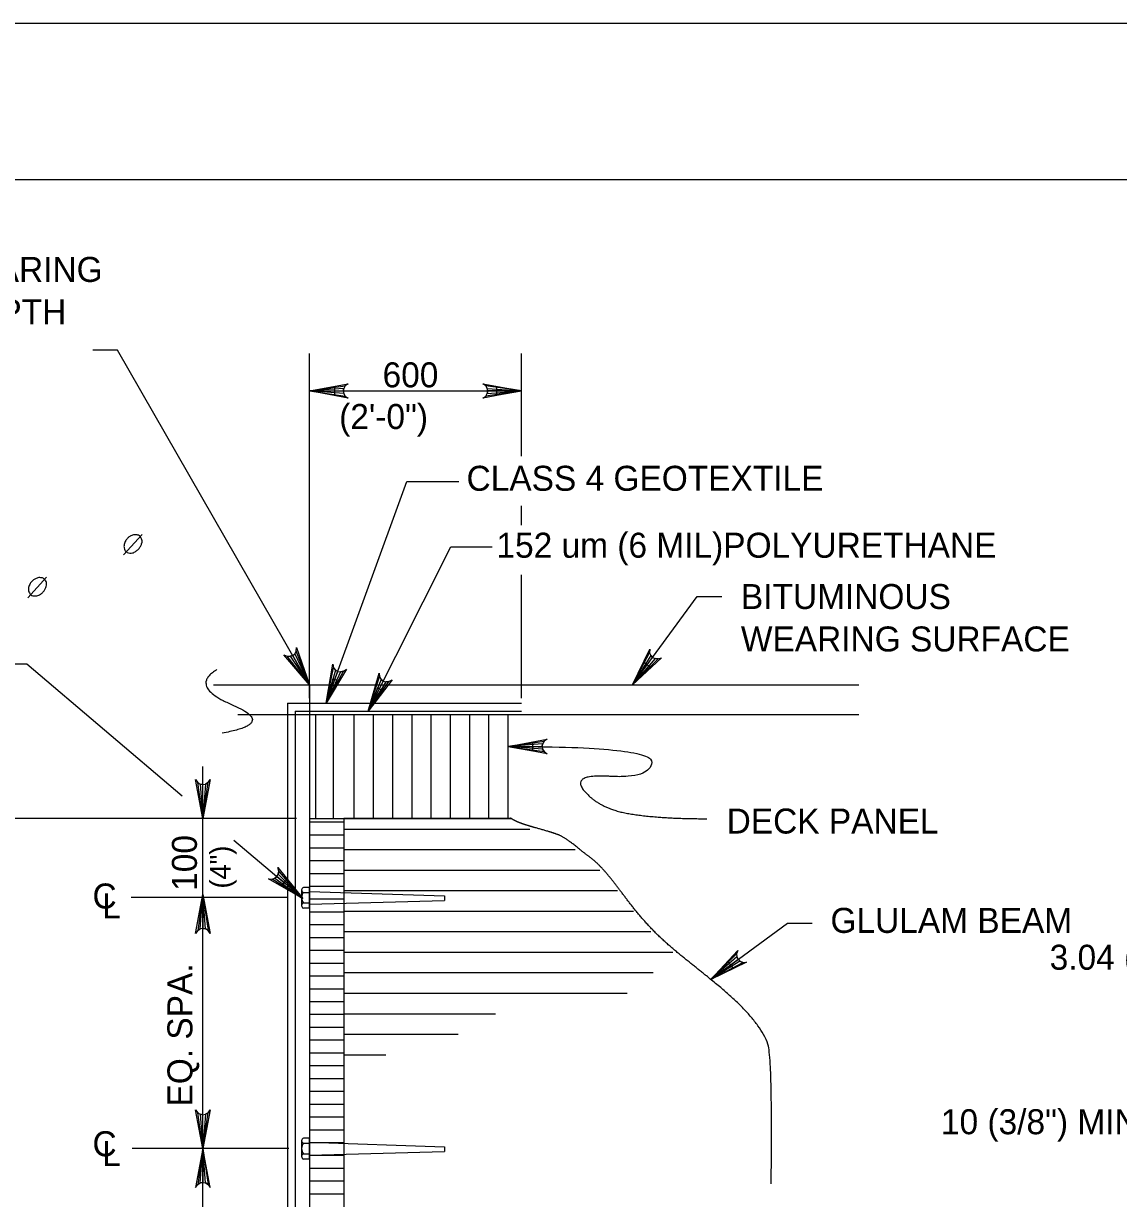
# Model space of a CAD drawing. Extents: x -13 to 81, y -176 to 0.
# Drawn here: x 47.85 to 53.11, y -5.64 to 0 of the extents above; entities that cross this region are included whole.
import ezdxf

# ---------------------------------------------------------------- set-up
doc = ezdxf.new("R2010")
doc.units = 0
for name, color, linetype in [('Level 1', 7, 'Continuous'), ('Level 3', 7, 'Continuous'), ('Level 4', 7, 'Continuous'), ('Level 5', 7, 'Continuous'), ('Level 52', 7, 'Continuous'), ('Level 63', 7, 'Continuous'), ('Level 7', 7, 'Continuous')]:
    doc.layers.add(name, color=color, linetype=linetype)

msp = doc.modelspace()

# ---------------------------------------------------------------- linework, layer by layer
at = {"layer": 'Level 1'}
msp.add_lwpolyline([(35.75, -21.25), (67.25, -21.25), (67.25, -0.75), (35.75, -0.75)], close=True, dxfattribs=at)
at = {"layer": 'Level 3'}
for p, q in [((49.2237, -3.2382), (49.2237, -1.5837)), ((50.2417, -2.0767), (50.2417, -1.5837)), ((49.2237, -1.7637), (50.2417, -1.7637)), ((49.6906, -2.1984), (49.9411, -2.1984)), ((50.2417, -2.4084), (50.2417, -2.3154)), ((49.903, -2.5117), (50.1011, -2.5117)), ((50.2417, -3.2382), (50.2417, -2.646)), ((50.7744, -3.1736), (51.0846, -2.7508)), ((51.0846, -2.7508), (51.2027, -2.7508)), ((47.8689, -3.0749), (47.6388, -3.0749)), ((48.6134, -3.709), (47.8689, -3.0749)), ((48.7129, -4.1953), (48.7129, -3.5662)), ((49.1623, -3.8148), (47.2889, -3.8148)), ((49.1074, -4.1297), (48.8619, -3.9206)), ((49.1163, -4.1953), (48.3682, -4.1953)), ((48.7129, -5.2816), (48.7129, -4.1807)), ((51.1491, -4.5874), (51.5173, -4.3172)), ((51.5173, -4.3172), (51.6354, -4.3172)), ((49.1248, -5.3997), (48.3735, -5.3997)), ((48.7129, -6.6186), (48.7129, -5.3997))]:
    msp.add_line(p, q, dxfattribs=at)
for points in [[(49.2237, -1.7637), (49.4102, -1.7288), (49.3958, -1.7388), (49.3884, -1.7512), (49.3862, -1.7637), (49.3884, -1.7762), (49.3958, -1.7887), (49.4102, -1.7987), (49.2237, -1.7637), (49.3958, -1.7887), (49.3884, -1.7762), (49.2237, -1.7637), (49.3862, -1.7637), (49.3884, -1.7512), (49.2237, -1.7637), (49.3958, -1.7388)], [(50.2417, -1.7637), (50.0553, -1.7987), (50.0696, -1.7887), (50.077, -1.7762), (50.0792, -1.7637), (50.077, -1.7512), (50.0696, -1.7388), (50.0553, -1.7288), (50.2417, -1.7637), (50.0696, -1.7388), (50.077, -1.7512), (50.2417, -1.7637), (50.0792, -1.7637), (50.077, -1.7762), (50.2417, -1.7637), (50.0696, -1.7887)], [(49.3048, -3.2621), (49.6907, -2.1984)], [(49.5052, -3.3007), (49.9031, -2.5117)], [(50.7744, -3.1736), (50.8565, -3.0026), (50.856, -3.0201), (50.8618, -3.0334), (50.8705, -3.0426), (50.8819, -3.0482), (50.8963, -3.0497), (50.9128, -3.0439), (50.7744, -3.1736), (50.8963, -3.0497), (50.8819, -3.0482), (50.7744, -3.1736), (50.8705, -3.0426), (50.8618, -3.0334), (50.7744, -3.1736), (50.856, -3.0201)], [(49.3048, -3.2621), (49.3356, -3.0749), (49.34, -3.0918), (49.3492, -3.1031), (49.3603, -3.1093), (49.3727, -3.1116), (49.387, -3.1088), (49.4012, -3.0987), (49.3048, -3.2621), (49.387, -3.1088), (49.3727, -3.1116), (49.3048, -3.2621), (49.3603, -3.1093), (49.3492, -3.1031), (49.3048, -3.2621), (49.34, -3.0918)], [(49.5052, -3.3007), (49.558, -3.1185), (49.5604, -3.1357), (49.5682, -3.148), (49.5784, -3.1556), (49.5905, -3.1593), (49.605, -3.1583), (49.6204, -3.1499), (49.5052, -3.3007), (49.605, -3.1583), (49.5905, -3.1593), (49.5052, -3.3007), (49.5784, -3.1556), (49.5682, -3.148), (49.5052, -3.3007), (49.5604, -3.1357)], [(50.1774, -3.4695), (50.3638, -3.4346), (50.3495, -3.4445), (50.3421, -3.457), (50.3399, -3.4695), (50.3421, -3.482), (50.3495, -3.4945), (50.3638, -3.5044), (50.1774, -3.4695), (50.3495, -3.4945), (50.3421, -3.482), (50.1774, -3.4695), (50.3399, -3.4695), (50.3421, -3.457), (50.1774, -3.4695), (50.3495, -3.4445)], [(48.7129, -3.8148), (48.678, -3.6283), (48.6879, -3.6427), (48.7004, -3.6501), (48.7129, -3.6522), (48.7254, -3.6501), (48.7379, -3.6427), (48.7478, -3.6283), (48.7129, -3.8148), (48.7379, -3.6427), (48.7254, -3.6501), (48.7129, -3.8148), (48.7129, -3.6522), (48.7004, -3.6501), (48.7129, -3.8148), (48.6879, -3.6427)], [(48.7129, -4.1807), (48.7478, -4.3672), (48.7379, -4.3528), (48.7254, -4.3454), (48.7129, -4.3433), (48.7004, -4.3454), (48.6879, -4.3528), (48.678, -4.3672), (48.7129, -4.1807), (48.6879, -4.3528), (48.7004, -4.3454), (48.7129, -4.1807), (48.7129, -4.3433), (48.7254, -4.3454), (48.7129, -4.1807), (48.7379, -4.3528)], [(51.1491, -4.5874), (51.2787, -4.449), (51.273, -4.4655), (51.2744, -4.4799), (51.2801, -4.4913), (51.2892, -4.5001), (51.3026, -4.5058), (51.3201, -4.5053), (51.1491, -4.5874), (51.3026, -4.5058), (51.2892, -4.5001), (51.1491, -4.5874), (51.2801, -4.4913), (51.2744, -4.4799), (51.1491, -4.5874), (51.273, -4.4655)], [(48.7129, -5.3997), (48.678, -5.2132), (48.6879, -5.2276), (48.7004, -5.235), (48.7129, -5.2372), (48.7254, -5.235), (48.7379, -5.2276), (48.7478, -5.2132), (48.7129, -5.3997), (48.7379, -5.2276), (48.7254, -5.235), (48.7129, -5.3997), (48.7129, -5.2372), (48.7004, -5.235), (48.7129, -5.3997), (48.6879, -5.2276)], [(48.7129, -5.3997), (48.678, -5.5861), (48.6879, -5.5717), (48.7004, -5.5643), (48.7129, -5.5622), (48.7254, -5.5643), (48.7379, -5.5717), (48.7478, -5.5861), (48.7129, -5.3997), (48.7379, -5.5717), (48.7254, -5.5643), (48.7129, -5.3997), (48.7129, -5.5622), (48.7004, -5.5643), (48.7129, -5.3997), (48.6879, -5.5717)]]:
    msp.add_lwpolyline(points, dxfattribs=at)
for points in [[(49.3438, -1.7437), (49.3438, -1.7837), (49.2237, -1.7637)], [(50.1217, -1.7437), (50.1217, -1.7837), (50.2417, -1.7637)], [(50.8601, -3.09), (50.8283, -3.0667), (50.7743, -3.1736)], [(49.3048, -3.2621), (49.3552, -3.1527), (49.3363, -3.1459)], [(49.5052, -3.3007), (49.5682, -3.198), (49.5503, -3.189)], [(50.2952, -3.491), (50.2958, -3.4516), (50.1774, -3.4695)], [(49.1148, -4.1072), (49.0892, -4.1372), (49.1919, -4.1987)], [(51.2562, -4.5333), (51.2329, -4.5016), (51.1493, -4.5873)]]:
    msp.add_lwpolyline(points, close=True, dxfattribs=at)
msp.add_open_spline([(50.1774, -3.4695), (50.8787, -3.4695), (50.8548, -3.6251), (50.4722, -3.6011), (50.6157, -3.7687), (50.9027, -3.8165), (51.1298, -3.8165)], degree=2, dxfattribs=at)
at = {"layer": 'Level 4'}
for p, q in [((48.3314, -2.5499), (48.421, -2.4518)), ((47.8732, -2.7559), (47.9627, -2.6578))]:
    msp.add_line(p, q, dxfattribs=at)
for points in [[(48.4117, -2.4615), (48.4047, -2.4561), (48.3977, -2.4542), (48.389, -2.4534), (48.3838, -2.4534), (48.3753, -2.4553), (48.3673, -2.459), (48.3619, -2.4621), (48.3513, -2.4706), (48.343, -2.4813), (48.338, -2.4914), (48.3351, -2.5007), (48.3342, -2.5093), (48.3351, -2.5167), (48.3387, -2.5272), (48.3426, -2.5327), (48.3502, -2.5386), (48.3618, -2.5413), (48.375, -2.5409), (48.3918, -2.5332), (48.4039, -2.5228), (48.4131, -2.5101), (48.4191, -2.4968), (48.4211, -2.4822), (48.4185, -2.4727), (48.4122, -2.4615)], [(47.9535, -2.6675), (47.9464, -2.6621), (47.9394, -2.6602), (47.9307, -2.6594), (47.9256, -2.6594), (47.9171, -2.6613), (47.9091, -2.665), (47.9037, -2.6681), (47.8931, -2.6766), (47.8847, -2.6873), (47.8798, -2.6974), (47.8768, -2.7067), (47.8759, -2.7153), (47.8768, -2.7227), (47.8805, -2.7332), (47.8843, -2.7387), (47.8919, -2.7446), (47.9035, -2.7473), (47.9168, -2.7469), (47.9335, -2.7392), (47.9457, -2.7288), (47.9548, -2.7161), (47.9608, -2.7028), (47.9628, -2.6882), (47.9602, -2.6787), (47.9539, -2.6675)]]:
    msp.add_spline(points, degree=3, dxfattribs=at)
at = {"layer": 'Level 5'}
for p, q in [((48.3036, -1.567), (48.1855, -1.567)), ((49.2248, -3.1736), (48.3036, -1.567)), ((48.763, -3.1736), (51.8598, -3.1736)), ((49.2237, -3.1736), (49.2237, -7.0929)), ((49.119, -3.2621), (50.2417, -3.2621)), ((49.119, -3.2621), (49.119, -7.198)), ((49.2545, -3.3184), (48.88, -3.3184)), ((49.156, -3.3007), (50.2417, -3.3007)), ((49.156, -3.3007), (49.156, -7.1582)), ((51.8598, -3.3184), (49.2237, -3.3184)), ((49.2237, -3.8148), (50.1907, -3.8148)), ((49.3892, -3.8148), (49.3892, -7.0929)), ((49.1863, -4.1578), (49.1863, -4.2337)), ((49.2237, -4.1655), (49.8712, -4.1874)), ((49.2237, -4.227), (49.8712, -4.2095)), ((49.8712, -4.1874), (49.8712, -4.2095)), ((49.1863, -5.3617), (49.1863, -5.4376)), ((49.2237, -5.3694), (49.8712, -5.3912)), ((49.2237, -5.4308), (49.8712, -5.4134)), ((49.8712, -5.3912), (49.8712, -5.4134))]:
    msp.add_line(p, q, dxfattribs=at)
for points in [[(49.2248, -3.1736), (49.1017, -3.0292), (49.1175, -3.0368), (49.132, -3.037), (49.1439, -3.0326), (49.1537, -3.0245), (49.1608, -3.0119), (49.1623, -2.9945), (49.2248, -3.1736), (49.1608, -3.0119), (49.1537, -3.0245), (49.2248, -3.1736), (49.1439, -3.0326), (49.132, -3.037), (49.2248, -3.1736), (49.1175, -3.0368)], [(50.1907, -3.8148), (50.1743, -3.8148), (49.3892, -3.8148), (49.3892, -6.3787)]]:
    msp.add_lwpolyline(points, dxfattribs=at)
for centre, radius, start, end in [((49.1989, -4.1583), 0.0126, 107.4518, 252.5482), ((49.226, -4.1953), 0.0397, 141.05, 218.95), ((49.2002, -4.2333), 0.0139, 111.2869, 178.1729), ((49.2002, -4.2333), 0.0139, 178.1729, 248.7131), ((49.1989, -5.3622), 0.0126, 107.4518, 252.5482), ((49.226, -5.3992), 0.0397, 141.05, 218.95), ((49.2002, -5.4372), 0.0139, 111.2869, 178.1729), ((49.2002, -5.4372), 0.0139, 178.1729, 248.7131)]:
    msp.add_arc(centre, radius, start, end, dxfattribs=at)
msp.add_open_spline([(48.7797, -3.1011), (48.6452, -3.182), (49.067, -3.3602), (48.8058, -3.4058)], degree=2, dxfattribs=at)
at = {"layer": 'Level 52'}
msp.add_lwpolyline([(49.1919, -4.1987), (49.0273, -4.1045), (49.0448, -4.1063), (49.0585, -4.1015), (49.0682, -4.0934), (49.0747, -4.0825), (49.0772, -4.0682), (49.0727, -4.0512), (49.1919, -4.1987), (49.0772, -4.0682), (49.0747, -4.0825), (49.1919, -4.1987), (49.0682, -4.0934), (49.0585, -4.1015), (49.1919, -4.1987), (49.0448, -4.1063)], dxfattribs=at)
at = {"layer": 'Level 63'}
msp.add_lwpolyline([(34, -22), (68, -22), (68, 0), (34, 0)], close=True, dxfattribs=at)
at = {"layer": 'Level 7'}
for p, q in [((49.2545, -3.8148), (49.2545, -3.3184)), ((49.3388, -3.8148), (49.3388, -3.3184)), ((49.4393, -3.8148), (49.4393, -3.3184)), ((49.5315, -3.8148), (49.5315, -3.3184)), ((49.6238, -3.8148), (49.6238, -3.3184)), ((49.7161, -3.8148), (49.7161, -3.3184)), ((49.8083, -3.8148), (49.8083, -3.3184)), ((49.9007, -3.8148), (49.9007, -3.3184)), ((49.9929, -3.8148), (49.9929, -3.3184)), ((50.0852, -3.8148), (50.0852, -3.3184)), ((50.1774, -3.8148), (50.1774, -3.3184)), ((49.2237, -3.8148), (49.2237, -3.8148)), ((49.2237, -3.8317), (49.3892, -3.8317)), ((49.3892, -3.8148), (49.3892, -3.8148)), ((49.3892, -3.8663), (50.2809, -3.8663)), ((49.2237, -3.8941), (49.3892, -3.8941)), ((49.2237, -3.9556), (49.3892, -3.9556)), ((49.3894, -3.9647), (50.4993, -3.9647)), ((49.2237, -4.0172), (49.3892, -4.0172)), ((49.2237, -4.0787), (49.3892, -4.0787)), ((49.3896, -4.0632), (50.617, -4.0632)), ((49.2237, -4.1463), (49.1952, -4.1463)), ((49.1952, -4.1703), (49.2237, -4.1703)), ((49.2237, -4.1402), (49.3892, -4.1402)), ((49.2237, -4.2462), (49.2237, -4.1463)), ((49.3897, -4.1616), (50.7012, -4.1616)), ((49.1952, -4.2203), (49.2237, -4.2203)), ((49.2237, -4.2017), (49.3892, -4.2017)), ((49.2237, -4.2462), (49.1952, -4.2462)), ((49.2237, -4.2632), (49.3892, -4.2632)), ((49.39, -4.26), (50.7781, -4.26)), ((49.2237, -4.3247), (49.3892, -4.3247)), ((49.2237, -4.3862), (49.3892, -4.3862)), ((49.3902, -4.3585), (50.8622, -4.3585)), ((49.2237, -4.4478), (49.3892, -4.4478)), ((49.2237, -4.5092), (49.3892, -4.5092)), ((49.3903, -4.4569), (50.9671, -4.4569)), ((49.3906, -4.5553), (50.8735, -4.5553)), ((49.2237, -4.5707), (49.3892, -4.5707)), ((49.2237, -4.6322), (49.3892, -4.6322)), ((49.3907, -4.6537), (50.7475, -4.6537)), ((49.2237, -4.6938), (49.3892, -4.6938)), ((49.2237, -4.7553), (49.3892, -4.7553)), ((49.3909, -4.7522), (50.1163, -4.7522)), ((49.2237, -4.8168), (49.3892, -4.8168)), ((49.2237, -4.8783), (49.3892, -4.8783)), ((49.3911, -4.8506), (49.9368, -4.8506)), ((49.2237, -4.9398), (49.3892, -4.9398)), ((49.3913, -4.949), (49.5912, -4.949)), ((49.2237, -5.0014), (49.3892, -5.0014)), ((49.2237, -5.0629), (49.3892, -5.0629)), ((49.2237, -5.1244), (49.3892, -5.1244)), ((49.2237, -5.1859), (49.3892, -5.1859)), ((49.2237, -5.2474), (49.3892, -5.2474)), ((49.2237, -5.3502), (49.1952, -5.3502)), ((49.2237, -5.309), (49.3892, -5.309)), ((49.2237, -5.4501), (49.2237, -5.3502)), ((49.1952, -5.3742), (49.2237, -5.3742)), ((49.2237, -5.3705), (49.3892, -5.3705)), ((49.1952, -5.4242), (49.2237, -5.4242)), ((49.2237, -5.4501), (49.1952, -5.4501)), ((49.2237, -5.432), (49.3892, -5.432)), ((49.2237, -5.4935), (49.3892, -5.4935)), ((49.2237, -5.555), (49.3892, -5.555)), ((49.2237, -5.6165), (49.3892, -5.6165))]:
    msp.add_line(p, q, dxfattribs=at)
msp.add_open_spline([(51.4387, -5.5684), (51.4426, -5.3831), (51.4368, -4.9253), (51.4035, -4.8501), (51.353, -4.7783), (51.2893, -4.7093), (51.2165, -4.6428), (51.1382, -4.5782), (51.0587, -4.5151), (50.9818, -4.4528), (50.9114, -4.3912), (50.8506, -4.3297), (50.7982, -4.2692), (50.7521, -4.2107), (50.7103, -4.1553), (50.6709, -4.1039), (50.6317, -4.0576), (50.5907, -4.0172), (50.5457, -3.984), (50.4464, -3.9043), (50.393, -3.8845), (50.3392, -3.8686), (50.2875, -3.8544), (50.2407, -3.8398), (50.2015, -3.8229), (50.1886, -3.8132)], degree=2, dxfattribs=at)

# ---------------------------------------------------------------- texts
at = {"layer": 'Level 3'}
for s, p in [('SAW CUT BITUMINOUS WEARING', (45.6287, -1.2404)), ('SURFACE TO 40 (1 1/2") DEPTH', (45.6466, -1.4437)), ('600', (49.5749, -1.7462)), ('(2\'-0")', (49.3666, -1.9462)), ('CLASS 4 GEOTEXTILE', (49.9778, -2.2427)), ('152 um (6 MIL)POLYURETHANE', (50.1212, -2.5639)), ('BITUMINOUS', (51.2939, -2.8101)), ('WEARING SURFACE', (51.2939, -3.0139)), ('DECK PANEL', (51.2255, -3.8877)), ('C', (48.1832, -4.2475)), ('L', (48.2302, -4.2945)), ('GLULAM BEAM', (51.7237, -4.3645)), ('3.04 (11 GAGE) BONDED STEEL LAMINATE', (52.7752, -4.5414)), ('10 (3/8") MIN., 20 (13/16") MAX.', (52.2536, -5.3308)), ('C', (48.1832, -5.4364)), ('L', (48.2302, -5.4835))]:
    msp.add_text(s, height=0.12, dxfattribs=at).set_placement(p)
for s, height, p in [('100', 0.12, (48.6842, -4.1626)), ('(4")', 0.09774, (48.8453, -4.1518)), ('EQ. SPA.', 0.12, (48.6626, -5.1978))]:
    msp.add_text(s, height=height, rotation=90, dxfattribs=at).set_placement(p)

doc.saveas('drawing.dxf')
